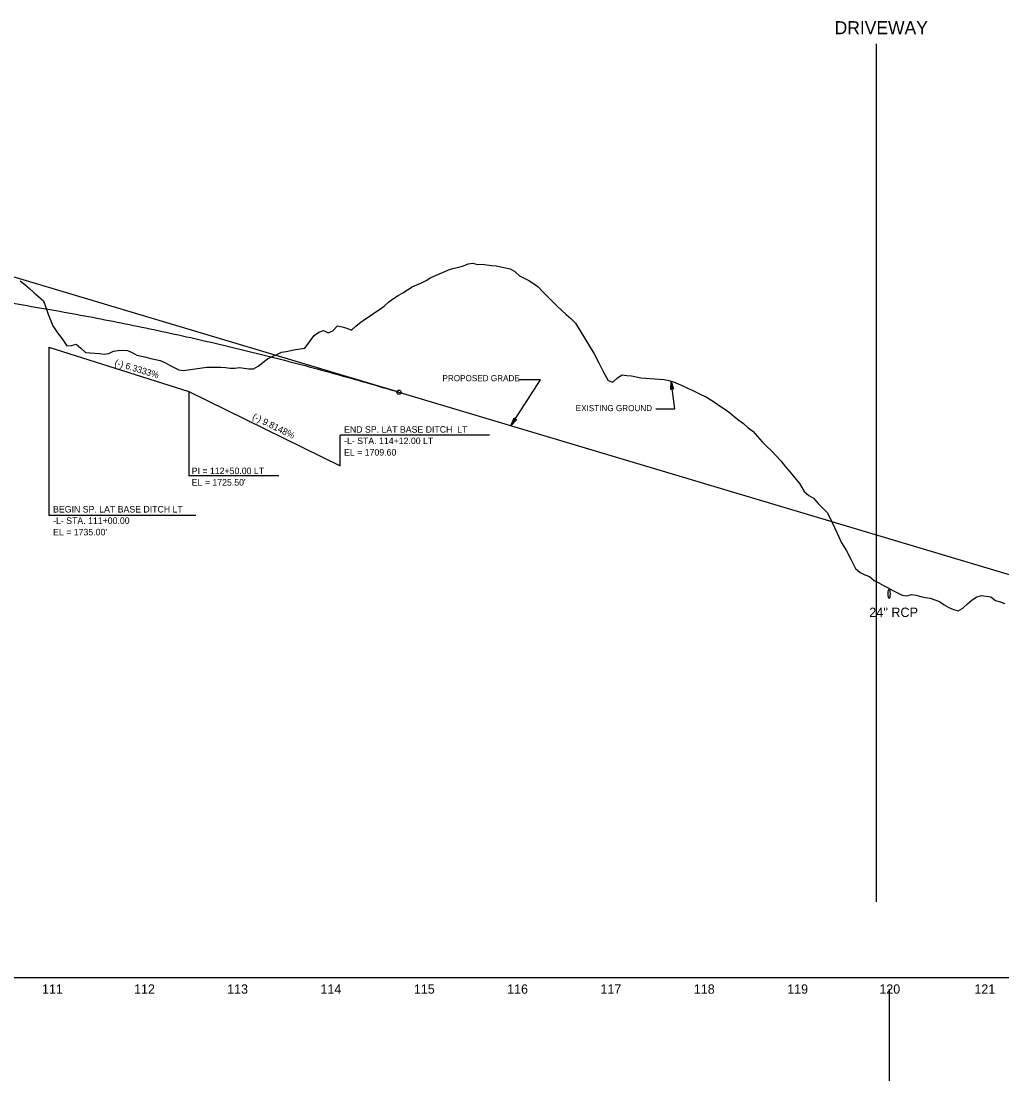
# Model space of a CAD drawing. Extents: x 498575 to 532350, y 405181 to 484585.
# Drawn here: x 515889 to 516940, y 483123 to 484258 of the extents above; entities that cross this region are included whole.
import ezdxf

# ---------------------------------------------------------------- set-up
doc = ezdxf.new("R2010")
doc.units = 0
for name, color, linetype in [('Exist Profile Cell', 7, 'Continuous'), ('Exist Vertical Profile Ground Line', 7, 'Continuous'), ('Exist Vertical Profile Horizontal Axis Label Major', 7, 'Continuous'), ('Prop Drainage Structure Pipe Welded Steel 54in Label', 7, 'Continuous'), ('Prop PFL Text', 7, 'Continuous'), ('Prop Vertical Profile Curve Label', 7, 'Continuous'), ('Prop Vertical Profile Ditch Grade Left', 7, 'Continuous'), ('Prop Vertical Profile Ditch Grade Left Label', 7, 'Continuous'), ('Prop Vertical Profile Grade', 7, 'Continuous'), ('Prop VPI Label', 7, 'Continuous'), ('Scratch_Level_2', 7, 'Continuous'), ('Sheet Profile Grid Minor CELL', 7, 'Continuous')]:
    doc.layers.add(name, color=color, linetype=linetype)

msp = doc.modelspace()

# ---------------------------------------------------------------- linework, layer by layer
at = {"layer": 'Exist Profile Cell'}
msp.add_line((505856.7, 483233.7), (526056.7, 483233.7), dxfattribs=at)
at = {"layer": 'Exist Vertical Profile Ground Line'}
for points in [[(516313.2, 483975.8), (516318.2, 483977.7), (516323.2, 483980.4), (516328.2, 483983.5), (516333.2, 483985.8), (516338.2, 483987.8), (516343.2, 483990), (516348.2, 483992.2), (516353.2, 483993.3), (516358.2, 483994.5), (516363.2, 483996), (516368.2, 483998.1), (516373.2, 483999), (516378.2, 483997.5), (516383.2, 483997.6), (516388.2, 483997), (516393.2, 483996.5), (516398.2, 483996.1), (516403.2, 483995), (516408.2, 483994), (516413.2, 483992.8), (516418.2, 483989.9), (516423.2, 483985.4), (516428.2, 483982.8), (516433.2, 483980.4), (516438.2, 483977.2), (516443.2, 483973.4), (516448.2, 483968.3), (516453.2, 483963.3), (516458.2, 483958.2), (516463.2, 483953), (516468.2, 483948.5), (516473.2, 483944), (516478.2, 483939.5), (516483.2, 483934.7), (516488.2, 483926.3), (516493.2, 483918), (516498.2, 483909.9), (516503.2, 483901.8), (516508.2, 483891.9), (516513.2, 483881.9), (516518.2, 483873.2), (516523.2, 483871.4), (516528.2, 483876.1), (516533.2, 483879.2), (516538.2, 483878.6), (516543.2, 483878), (516548.2, 483876.9), (516553.2, 483876), (516558.2, 483875.5), (516563.2, 483875.1), (516568.2, 483875), (516573.2, 483874.6), (516578.2, 483874.1), (516583.2, 483873.3), (516588.2, 483871.6), (516593.2, 483869.7), (516598.2, 483867.4), (516603.2, 483865), (516608.2, 483862.6), (516613.2, 483860.1), (516618.2, 483857.9), (516623.2, 483855.5), (516628.2, 483852.5), (516633.2, 483849.2), (516638.2, 483845.8), (516643.2, 483842.3), (516648.2, 483838.8), (516653.2, 483834.7), (516658.2, 483830.6), (516663.2, 483826.9), (516668.2, 483822.3), (516673.2, 483818.7), (516678.2, 483813.2), (516683.2, 483807.4), (516688.2, 483802.6), (516693.2, 483797.9), (516698.2, 483792.4), (516703.2, 483786.9), (516708.2, 483780.8), (516713.2, 483774.8), (516718.2, 483769), (516723.2, 483762.9), (516728.2, 483754.2), (516733.2, 483750.1), (516738.2, 483746.9), (516743.2, 483741.4), (516748.2, 483736.4), (516753.2, 483731.3), (516758.2, 483721), (516763.2, 483710.2), (516768.2, 483699.4), (516773.2, 483691.2), (516778.2, 483681.9), (516783.2, 483671.6), (516788.2, 483667.3), (516793.2, 483664.8), (516798.2, 483663), (516803.2, 483659), (516808.2, 483656.3), (516813.2, 483653.5)], [(515888.2, 483979.8), (515893.2, 483976), (515898.2, 483971.6), (515903.2, 483967.2), (515908.2, 483962.8), (515913.2, 483958.5), (515918.2, 483944.2), (515923.2, 483931.6), (515928.2, 483924.3), (515933.2, 483917.9), (515938.2, 483910.3), (515943.2, 483910.6), (515948.2, 483912.1), (515953.2, 483907.8), (515958.2, 483903.1), (515963.2, 483902.7), (515968.2, 483902.3), (515973.2, 483901.9), (515978.2, 483901.3), (515983.2, 483902), (515988.2, 483904.5), (515993.2, 483905.1), (515998.2, 483905.7), (516003.2, 483905.4), (516008.2, 483903.2), (516013.2, 483900.4), (516018.2, 483899.2), (516023.2, 483898), (516028.2, 483896.8), (516033.2, 483895.6), (516038.2, 483894.6), (516043.2, 483892.5), (516048.2, 483889.7), (516053.2, 483886.9), (516058.2, 483884.5), (516063.2, 483884), (516068.2, 483884.4), (516073.2, 483885.2), (516078.2, 483885.9), (516083.2, 483886.6), (516088.2, 483887.4), (516093.2, 483887.5), (516098.2, 483887.5), (516103.2, 483887.5), (516108.2, 483887.1), (516113.2, 483886.3), (516118.2, 483886.3), (516123.2, 483886.9), (516128.2, 483886.2), (516133.2, 483885.5), (516138.2, 483885.6), (516143.2, 483888.4), (516148.2, 483892.3), (516153.2, 483896.2), (516158.2, 483898.8), (516163.2, 483901), (516168.2, 483903.5), (516173.2, 483904.3), (516178.2, 483905.3), (516183.2, 483906.3), (516188.2, 483907), (516193.2, 483907.7), (516198.2, 483914.4), (516203.2, 483921.5), (516208.2, 483925), (516213.2, 483926.7), (516218.2, 483924.3), (516223.2, 483926.5), (516228.2, 483931.7), (516233.2, 483930.6), (516238.2, 483929.1), (516243.2, 483927.1), (516248.2, 483931.8), (516253.2, 483935.5), (516258.2, 483939.1), (516263.2, 483942.5), (516268.2, 483945.9), (516273.2, 483949.2), (516278.2, 483952.9), (516283.2, 483957.3), (516288.2, 483960.9), (516293.2, 483964.3), (516298.2, 483967.1), (516303.2, 483970.2), (516308.2, 483973.5), (516313.2, 483975.8)], [(516813.2, 483653.5), (516818.2, 483651), (516823.2, 483648), (516828.2, 483645.6), (516833.2, 483643.2), (516838.2, 483642.4), (516843.2, 483644), (516848.2, 483643), (516853.2, 483641.6), (516858.2, 483640.5), (516863.2, 483639.9), (516868.2, 483638), (516873.2, 483636.3), (516878.2, 483632.8), (516883.2, 483630), (516888.2, 483627.8), (516893.2, 483626.2), (516898.2, 483629.3), (516903.2, 483633.8), (516908.2, 483638.3), (516913.2, 483641.2), (516918.2, 483642.9), (516923.2, 483642.1), (516928.2, 483641.3), (516933.2, 483637.3), (516938.2, 483635.9), (516943.2, 483634.3)]]:
    msp.add_lwpolyline(points, dxfattribs=at)
at = {"layer": 'Prop Drainage Structure Pipe Welded Steel 54in Label'}
msp.add_ellipse((516819.1, 483644.7), major_axis=(0, 5), ratio=0.2, dxfattribs=at)
at = {"layer": 'Prop PFL Text'}
for p, q in [((516414.1, 483824.7), (516445.7, 483873.9)), ((516445.7, 483873.9), (516422.3, 483873.9)), ((516589.6, 483842.9), (516585.5, 483872.5)), ((516569.2, 483842.9), (516589.6, 483842.9))]:
    msp.add_line(p, q, dxfattribs=at)
for points in [[(516585.2, 483863.4), (516585.5, 483872.5), (516588.3, 483863.8), (516586.6, 483864.7)], [(516420.3, 483831.5), (516414.1, 483824.7), (516417.6, 483833.3), (516418.4, 483831.4)]]:
    msp.add_lwpolyline(points, close=True, dxfattribs=at)
at = {"layer": 'Prop Vertical Profile Curve Label'}
msp.add_circle((516294.1, 483860.6), 2.25, dxfattribs=at)
at = {"layer": 'Prop Vertical Profile Ditch Grade Left'}
msp.add_lwpolyline([(515919.1, 483908.7), (516069.1, 483861.2), (516231.1, 483781.7)], dxfattribs=at)
at = {"layer": 'Prop Vertical Profile Ditch Grade Left Label'}
for p, q in [((515919.1, 483908.7), (515919.1, 483729)), ((516069.1, 483861.2), (516069.1, 483771)), ((516390.9, 483814.4), (516231.1, 483814.4)), ((516231.1, 483781.7), (516231.1, 483814.4)), ((516165.5, 483771), (516069.1, 483771)), ((515919.1, 483729), (516076.4, 483729))]:
    msp.add_line(p, q, dxfattribs=at)
at = {"layer": 'Prop Vertical Profile Grade'}
msp.add_line((516294.1, 483860.6), (516969.1, 483659), dxfattribs=at)
msp.add_spline([(514544.1, 483877.4), (514579.1, 483886.9), (514614.1, 483896.1), (514649.1, 483904.9), (514684.1, 483913.3), (514719.1, 483921.2), (514754.1, 483928.8), (514789.1, 483935.9), (514824.1, 483942.7), (514859.1, 483949), (514894.1, 483955), (514929.1, 483960.5), (514964.1, 483965.6), (514999.1, 483970.4), (515034.1, 483974.7), (515069.1, 483978.6), (515104.1, 483982.1), (515139.1, 483985.2), (515174.1, 483987.9), (515209.1, 483990.2), (515244.1, 483992.1), (515279.1, 483993.6), (515314.1, 483994.7), (515349.1, 483995.4), (515384.1, 483995.6), (515419.1, 483995.5), (515454.1, 483995), (515489.1, 483994), (515524.1, 483992.7), (515559.1, 483990.9), (515594.1, 483988.8), (515629.1, 483986.2), (515664.1, 483983.2), (515699.1, 483979.9), (515734.1, 483976.1), (515769.1, 483971.9), (515804.1, 483967.3), (515839.1, 483962.3), (515874.1, 483956.9), (515909.1, 483951.1), (515944.1, 483944.9), (515979.1, 483938.3), (516014.1, 483931.3), (516049.1, 483923.9), (516084.1, 483916.1), (516119.1, 483907.8), (516154.1, 483899.2), (516189.1, 483890.2), (516224.1, 483880.7), (516259.1, 483870.9), (516294.1, 483860.6)], degree=3, dxfattribs=at)
at = {"layer": 'Prop VPI Label'}
msp.add_line((516294.1, 483860.6), (515421.7, 484121.2), dxfattribs=at)
at = {"layer": 'Scratch_Level_2'}
msp.add_line((516805.1, 484233.7), (516805.1, 483314.6), dxfattribs=at)
at = {"layer": 'Sheet Profile Grid Minor CELL'}
msp.add_line((516819.1, 483221.2), (516819.1, 483122.9), dxfattribs=at)

# ---------------------------------------------------------------- texts
at = {"layer": 'Exist Vertical Profile Horizontal Axis Label Major'}
for s, p in [('111', (515911.7, 483216.2)), ('111', (515911.7, 483216.2)), ('112', (516010.3, 483216.2)), ('112', (516010.3, 483216.2)), ('113', (516110.1, 483216.2)), ('113', (516110.1, 483216.2)), ('114', (516210, 483216.2)), ('114', (516210, 483216.2)), ('115', (516310.1, 483216.2)), ('115', (516310.1, 483216.2)), ('116', (516410, 483216.2)), ('116', (516410, 483216.2)), ('117', (516509.9, 483216.2)), ('117', (516509.9, 483216.2)), ('118', (516610, 483216.2)), ('118', (516610, 483216.2)), ('119', (516710, 483216.2)), ('119', (516710, 483216.2)), ('120', (516808.7, 483216.2)), ('120', (516808.7, 483216.2)), ('121', (516910.5, 483216.2)), ('121', (516910.5, 483216.2))]:
    msp.add_text(s, height=10, dxfattribs=at).set_placement(p)
at = {"layer": 'Prop Drainage Structure Pipe Welded Steel 54in Label'}
msp.add_text('24" RCP', height=10.12, dxfattribs=at).set_placement((516797.9, 483619.7))
at = {"layer": 'Prop PFL Text'}
for s, p in [('PROPOSED GRADE', (516340.7, 483872.4)), ('EXISTING GROUND', (516483.4, 483840.3))]:
    msp.add_text(s, height=6.516, dxfattribs=at).set_placement(p)
at = {"layer": 'Prop Vertical Profile Ditch Grade Left Label'}
for s, rotation, p in [('(-) 6.3333%', 343.0713, (515988.9, 483889.4)), ('(-) 9.8148%', 333.6748, (516136.4, 483832.1)), ('END SP. LAT BASE DITCH  LT', 360, (516235.3, 483817.2)), ('-L- STA. 114+12.00 LT', 360, (516235.3, 483805)), ('EL = 1709.60', 360, (516235.3, 483792.7)), ('PI = 112+50.00 LT', 360, (516072.1, 483772.8)), ("EL = 1725.50'", 360, (516072.1, 483760.5)), ('BEGIN SP. LAT BASE DITCH LT', 360, (515923.6, 483731.7)), ('-L- STA. 111+00.00', 360, (515923.6, 483719.5)), ("EL = 1735.00'", 360, (515923.6, 483707.2))]:
    msp.add_text(s, height=7, rotation=rotation, dxfattribs=at).set_placement(p)
at = {"layer": 'Scratch_Level_2'}
msp.add_text('DRIVEWAY', height=14, dxfattribs=at).set_placement((516760.8, 484244.1))

doc.saveas('drawing.dxf')
